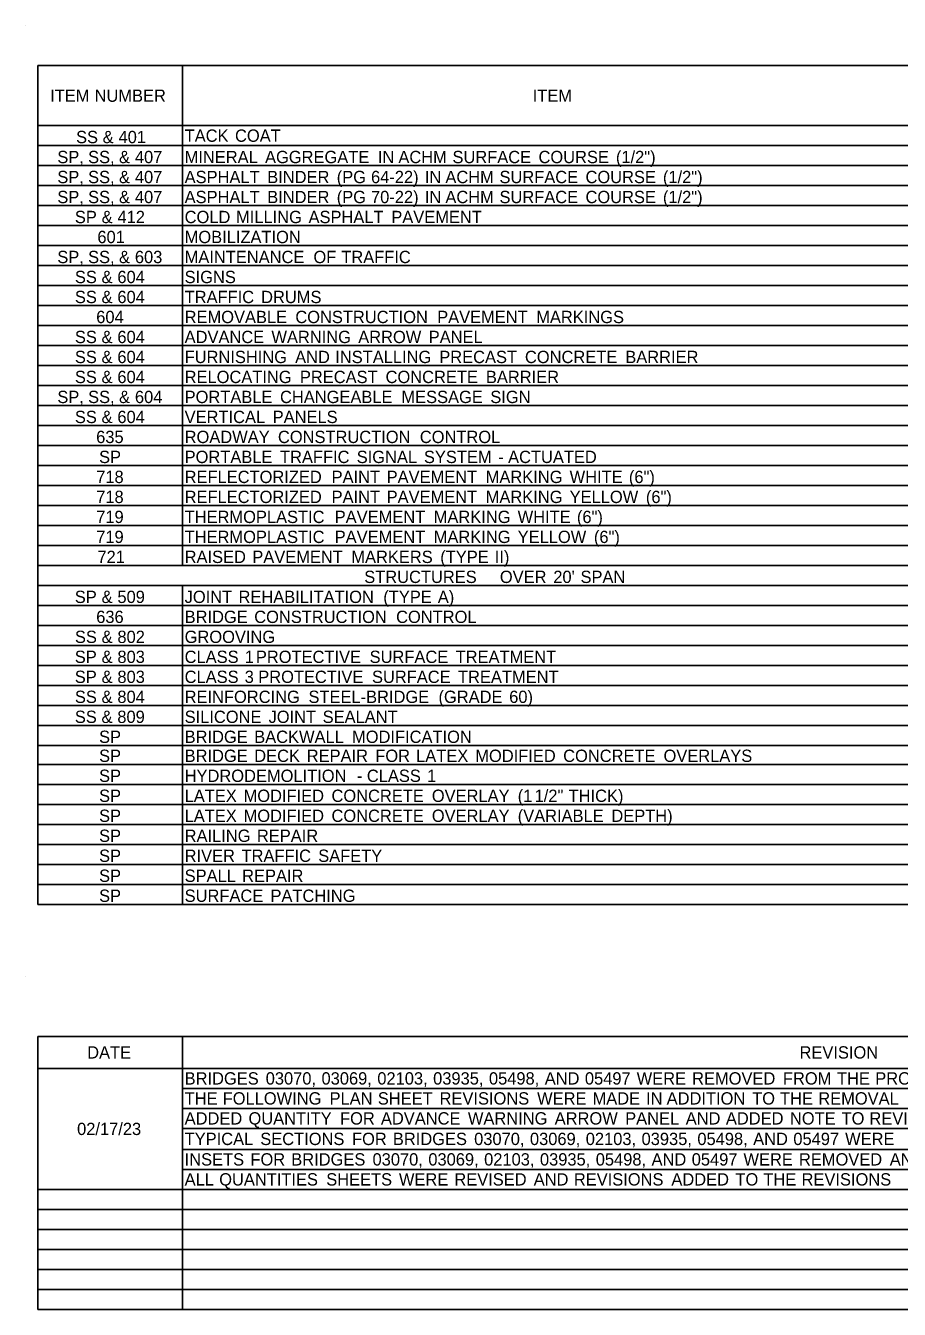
# Model space of a CAD drawing. Extents: x 544255 to 1930787, y -1947044 to 596640.
# Drawn here: x 555892 to 556318, y -1946820 to -1946194 of the extents above; entities that cross this region are included whole.
import ezdxf

# ---------------------------------------------------------------- set-up
doc = ezdxf.new("R2010")
doc.units = 0
doc.layers.add('Default', color=7, linetype='Continuous')

msp = doc.modelspace()

# ---------------------------------------------------------------- linework, layer by layer
at = {"layer": 'Default'}
for p, q in [((555892.13, -1946194.14), (555892.13, -1946194.14)), ((555897.98, -1946213.64), (556904.18, -1946213.64)), ((555897.98, -1946622.65), (555897.98, -1946213.64)), ((555897.98, -1946622.65), (555897.98, -1946213.64)), ((555968.66, -1946213.64), (556268.48, -1946213.64)), ((555968.66, -1946457.39), (555968.66, -1946213.64)), ((556268.48, -1946213.64), (556329.41, -1946213.64)), ((555897.98, -1946242.89), (556904.18, -1946242.89)), ((555897.98, -1946242.89), (556904.18, -1946242.89)), ((555968.66, -1946457.39), (555968.66, -1946242.89)), ((555897.98, -1946252.64), (556904.18, -1946252.64)), ((555897.98, -1946262.39), (556904.18, -1946262.39)), ((555897.98, -1946272.14), (556904.18, -1946272.14)), ((555897.98, -1946281.89), (556904.18, -1946281.89)), ((555897.98, -1946291.64), (556904.18, -1946291.64)), ((555897.98, -1946301.39), (556904.18, -1946301.39)), ((555897.98, -1946311.14), (556904.18, -1946311.14)), ((555897.98, -1946320.89), (556904.18, -1946320.89)), ((555897.98, -1946330.64), (556904.18, -1946330.64)), ((555897.98, -1946340.39), (556904.18, -1946340.39)), ((555897.98, -1946350.14), (556904.18, -1946350.14)), ((555897.98, -1946359.89), (556904.18, -1946359.89)), ((555897.98, -1946369.64), (556904.18, -1946369.64)), ((555897.98, -1946379.39), (556904.18, -1946379.39)), ((555897.98, -1946389.14), (556904.18, -1946389.14)), ((555897.98, -1946398.89), (556904.18, -1946398.89)), ((555897.98, -1946408.64), (556904.18, -1946408.64)), ((555897.98, -1946418.39), (556904.18, -1946418.39)), ((555897.98, -1946428.14), (556904.18, -1946428.14)), ((555897.98, -1946437.89), (556904.18, -1946437.89)), ((555897.98, -1946447.64), (556904.18, -1946447.64)), ((555897.98, -1946457.39), (556904.18, -1946457.39)), ((555897.98, -1946457.39), (556904.18, -1946457.39)), ((555897.98, -1946467.14), (556904.18, -1946467.14)), ((555897.98, -1946467.14), (556904.18, -1946467.14)), ((555968.66, -1946622.65), (555968.66, -1946467.14)), ((555897.98, -1946476.89), (556904.18, -1946476.89)), ((555897.98, -1946486.64), (556904.18, -1946486.64)), ((555897.98, -1946496.39), (556904.18, -1946496.39)), ((555897.98, -1946506.14), (556904.18, -1946506.14)), ((555897.98, -1946515.89), (556904.18, -1946515.89)), ((555897.98, -1946525.64), (556904.18, -1946525.64)), ((555897.98, -1946535.39), (556904.18, -1946535.39)), ((555897.98, -1946545.14), (556904.18, -1946545.14)), ((555897.98, -1946554.4), (556904.18, -1946554.4)), ((555897.98, -1946564.15), (556904.18, -1946564.15)), ((555897.98, -1946573.9), (556904.18, -1946573.9)), ((555897.98, -1946583.65), (556904.18, -1946583.65)), ((555897.98, -1946593.4), (556904.18, -1946593.4)), ((555897.98, -1946603.15), (556904.18, -1946603.15)), ((555897.98, -1946612.9), (556904.18, -1946612.9)), ((555897.98, -1946622.65), (556904.18, -1946622.65)), ((555892.13, -1946657.81), (555892.13, -1946657.81)), ((555897.98, -1946687.06), (556904.18, -1946687.06)), ((555897.98, -1946820.15), (555897.98, -1946687.06)), ((555897.98, -1946820.15), (555897.98, -1946687.06)), ((555968.66, -1946820.15), (555968.66, -1946687.06)), ((555897.98, -1946702.66), (556904.18, -1946702.66)), ((555968.66, -1946702.66), (556268.48, -1946702.66)), ((555968.66, -1946712.41), (556776.45, -1946712.41)), ((555968.66, -1946722.16), (556776.45, -1946722.16)), ((555968.66, -1946731.91), (556776.45, -1946731.91)), ((555968.66, -1946742.15), (556776.45, -1946742.15)), ((555968.66, -1946751.9), (556776.45, -1946751.9)), ((555897.98, -1946761.65), (556904.18, -1946761.65)), ((555897.98, -1946771.4), (556904.18, -1946771.4)), ((555897.98, -1946781.15), (556904.18, -1946781.15)), ((555897.98, -1946790.9), (556904.18, -1946790.9)), ((555897.98, -1946800.65), (556904.18, -1946800.65)), ((555897.98, -1946810.4), (556904.18, -1946810.4)), ((555897.98, -1946820.15), (556904.18, -1946820.15))]:
    msp.add_line(p, q, dxfattribs=at)

# ---------------------------------------------------------------- texts
for s, p in [('ITEM', (555904.07, -1946231.27)), (' NUMBER', (555923.49, -1946231.27)), ('ITEM', (556139.33, -1946231.27)), ('SS', (555916.7, -1946251.44)), (' &', (555927.45, -1946251.44)), (' 401', (555935.18, -1946251.44)), ('TACK', (555969.64, -1946250.77)), (' COAT', (555991.98, -1946250.77)), ('SP,', (555907.56, -1946261.19)), (' SS,', (555920.33, -1946261.19)), (' &', (555935.42, -1946261.19)), (' 407', (555943.15, -1946261.19)), ('MINERAL', (555969.64, -1946261.19)), (' AGGREGATE', (556006.61, -1946261.19)), (' IN', (556061.6, -1946261.19)), (' ACHM', (556071.63, -1946261.19)), (' SURFACE', (556098.01, -1946261.19)), (' COURSE', (556139.95, -1946261.19)), (' (1/2")', (556177.71, -1946261.19)), ('SP,', (555907.56, -1946270.94)), (' SS,', (555920.33, -1946270.94)), (' &', (555935.42, -1946270.94)), (' 407', (555943.15, -1946270.94)), ('ASPHALT', (555969.64, -1946270.94)), (' BINDER', (556007.68, -1946270.94)), (' (PG', (556041.57, -1946270.94)), (' 64-22)', (556058.28, -1946270.94)), (' IN', (556084.52, -1946270.94)), (' ACHM', (556094.55, -1946270.94)), (' SURFACE', (556120.93, -1946270.94)), (' COURSE', (556162.87, -1946270.94)), (' (1/2")', (556200.63, -1946270.94)), ('SP,', (555907.56, -1946280.69)), (' SS,', (555920.33, -1946280.69)), (' &', (555935.42, -1946280.69)), (' 407', (555943.15, -1946280.69)), ('ASPHALT', (555969.64, -1946280.69)), (' BINDER', (556007.68, -1946280.69)), (' (PG', (556041.57, -1946280.69)), (' 70-22)', (556058.28, -1946280.69)), (' IN', (556084.52, -1946280.69)), (' ACHM', (556094.55, -1946280.69)), (' SURFACE', (556120.93, -1946280.69)), (' COURSE', (556162.87, -1946280.69)), (' (1/2")', (556200.63, -1946280.69)), ('SP', (555916.11, -1946290.44)), (' &', (555926.93, -1946290.44)), (' 412', (555934.66, -1946290.44)), ('COLD', (555969.64, -1946290.44)), (' MILLING', (555992.48, -1946290.44)), (' ASPHALT', (556027.82, -1946290.44)), (' PAVEMENT', (556068.19, -1946290.44)), ('601', (555927.1, -1946300.19)), ('MOBILIZATION', (555969.64, -1946300.19)), ('SP,', (555907.56, -1946309.94)), (' SS,', (555920.33, -1946309.94)), (' &', (555935.42, -1946309.94)), (' 603', (555943.15, -1946309.94)), ('MAINTENANCE', (555969.64, -1946309.94)), (' OF', (556030.22, -1946309.94)), (' TRAFFIC', (556043.8, -1946309.94)), ('SS', (555916.13, -1946319.69)), (' &', (555926.88, -1946319.69)), (' 604', (555934.61, -1946319.69)), ('SIGNS', (555969.64, -1946319.69)), ('SS', (555916.13, -1946329.44)), (' &', (555926.88, -1946329.44)), (' 604', (555934.61, -1946329.44)), ('TRAFFIC', (555969.64, -1946329.44)), (' DRUMS', (556004.7, -1946329.44)), ('604', (555926.53, -1946339.19)), ('REMOVABLE', (555969.64, -1946339.19)), (' CONSTRUCTION', (556021.38, -1946339.19)), (' PAVEMENT', (556090.55, -1946339.19)), (' MARKINGS', (556138.84, -1946339.19)), ('SS', (555916.13, -1946348.94)), (' &', (555926.88, -1946348.94)), (' 604', (555934.61, -1946348.94)), ('ADVANCE', (555969.64, -1946348.94)), (' WARNING', (556009.73, -1946348.94)), (' ARROW', (556052.05, -1946348.94)), (' PANEL', (556086.42, -1946348.94)), ('SS', (555916.13, -1946358.69)), (' &', (555926.88, -1946358.69)), (' 604', (555934.61, -1946358.69)), ('FURNISHING', (555969.64, -1946358.69)), (' AND', (556021.28, -1946358.69)), (' INSTALLING', (556040.86, -1946358.69)), (' PRECAST', (556091.58, -1946358.69)), (' CONCRETE', (556133.34, -1946358.69)), (' BARRIER', (556182.27, -1946358.69)), ('SS', (555916.13, -1946368.44)), (' &', (555926.88, -1946368.44)), (' 604', (555934.61, -1946368.44)), ('RELOCATING', (555969.64, -1946368.44)), (' PRECAST', (556023.62, -1946368.44)), (' CONCRETE', (556065.38, -1946368.44)), (' BARRIER', (556114.31, -1946368.44)), ('SP,', (555907.57, -1946378.19)), (' SS,', (555920.34, -1946378.19)), (' &', (555935.44, -1946378.19)), (' 604', (555943.17, -1946378.19)), ('PORTABLE', (555969.64, -1946378.19)), (' CHANGEABLE', (556013.92, -1946378.19)), (' MESSAGE', (556073.11, -1946378.19)), (' SIGN', (556116.46, -1946378.19)), ('SS', (555916.13, -1946387.94)), (' &', (555926.88, -1946387.94)), (' 604', (555934.61, -1946387.94)), ('VERTICAL', (555969.64, -1946387.94)), (' PANELS', (556010.34, -1946387.94)), ('635', (555926.5, -1946397.69)), ('ROADWAY', (555969.64, -1946397.69)), (' CONSTRUCTION', (556012.9, -1946397.69)), (' CONTROL', (556082.08, -1946397.69)), ('SP', (555927.91, -1946407.44)), ('PORTABLE', (555969.64, -1946407.44)), (' TRAFFIC', (556013.92, -1946407.44)), (' SIGNAL', (556051.31, -1946407.44)), (' SYSTEM', (556084.09, -1946407.44)), (' ACTUATED', (556125.12, -1946407.44)), (' -', (556120.27, -1946407.44)), (' (6")', (556184.02, -1946417.19)), ('718', (555926.52, -1946417.19)), ('REFLECTORIZED', (555969.64, -1946417.19)), (' PAINT', (556039.07, -1946417.19)), (' PAVEMENT', (556065.91, -1946417.19)), (' MARKING', (556114.2, -1946417.19)), (' WHITE', (556155.13, -1946417.19)), ('718', (555926.52, -1946426.94)), ('REFLECTORIZED', (555969.64, -1946426.94)), (' PAINT', (556039.07, -1946426.94)), (' PAVEMENT', (556065.91, -1946426.94)), (' MARKING', (556114.2, -1946426.94)), (' YELLOW', (556155.13, -1946426.94)), (' (6")', (556192.3, -1946426.94)), ('719', (555926.52, -1946436.69)), ('THERMOPLASTIC', (555969.64, -1946436.69)), (' PAVEMENT', (556040.58, -1946436.69)), (' MARKING', (556088.86, -1946436.69)), (' WHITE', (556129.79, -1946436.69)), (' (6")', (556158.68, -1946436.69)), ('719', (555926.52, -1946446.44)), ('THERMOPLASTIC', (555969.64, -1946446.44)), (' PAVEMENT', (556040.58, -1946446.44)), (' MARKING', (556088.86, -1946446.44)), (' YELLOW', (556129.79, -1946446.44)), (' (6")', (556166.96, -1946446.44)), ('721', (555927.1, -1946456.19)), ('RAISED', (555969.64, -1946456.19)), (' PAVEMENT', (556000.41, -1946456.19)), (' MARKERS', (556048.69, -1946456.19)), (' (TYPE', (556092.05, -1946456.19)), (' II)', (556118.62, -1946456.19)), ('                                                                       STRUCTURES', (555898.95, -1946465.94)), (' OVER', (556121.11, -1946465.94)), (" 20'", (556147.16, -1946465.94)), (' SPAN', (556160.43, -1946465.94)), ('SP', (555916.08, -1946475.69)), (' &', (555926.9, -1946475.69)), (' 509', (555934.63, -1946475.69)), ('JOINT', (555969.64, -1946475.69)), (' REHABILITATION', (555993.69, -1946475.69)), (' (TYPE', (556064.28, -1946475.69)), (' A)', (556090.85, -1946475.69)), ('636', (555926.52, -1946485.44)), ('BRIDGE', (555969.64, -1946485.44)), (' CONSTRUCTION', (556001.34, -1946485.44)), (' CONTROL', (556070.51, -1946485.44)), ('SS', (555916.15, -1946495.19)), (' &', (555926.9, -1946495.19)), (' 802', (555934.63, -1946495.19)), ('GROOVING', (555969.64, -1946495.19)), ('SP', (555916.08, -1946504.94)), (' &', (555926.9, -1946504.94)), (' 803', (555934.63, -1946504.94)), ('CLASS', (555969.64, -1946504.94)), (' 1', (555996.69, -1946504.94)), (' PROTECTIVE', (556002.14, -1946504.94)), (' SURFACE', (556057.6, -1946504.94)), (' TREATMENT', (556099.54, -1946504.94)), ('SP', (555916.08, -1946514.69)), (' &', (555926.9, -1946514.69)), (' 803', (555934.63, -1946514.69)), ('CLASS', (555969.64, -1946514.69)), (' 3', (555996.69, -1946514.69)), (' PROTECTIVE', (556003.3, -1946514.69)), (' SURFACE', (556058.76, -1946514.69)), (' TREATMENT', (556100.7, -1946514.69)), ('SS', (555916.13, -1946524.44)), (' &', (555926.88, -1946524.44)), (' 804', (555934.61, -1946524.44)), ('REINFORCING', (555969.64, -1946524.44)), (' STEEL-BRIDGE', (556027.8, -1946524.44)), (' (GRADE', (556091.18, -1946524.44)), (' 60)', (556125.66, -1946524.44)), ('SS', (555916.11, -1946534.19)), (' &', (555926.86, -1946534.19)), (' 809', (555934.59, -1946534.19)), ('SILICONE', (555969.64, -1946534.19)), (' JOINT', (556008.32, -1946534.19)), (' SEALANT', (556034.7, -1946534.19)), ('SP', (555927.91, -1946543.94)), ('BRIDGE', (555969.64, -1946543.94)), (' BACKWALL', (556001.34, -1946543.94)), (' MODIFICATION', (556049.03, -1946543.94)), ('SP', (555927.91, -1946553.2)), ('BRIDGE', (555969.64, -1946553.2)), (' DECK', (556001.34, -1946553.2)), (' REPAIR', (556026.94, -1946553.2)), (' FOR', (556060.37, -1946553.2)), (' LATEX', (556080.28, -1946553.2)), (' MODIFIED', (556109.12, -1946553.2)), (' CONCRETE', (556151.98, -1946553.2)), (' OVERLAYS', (556200.91, -1946553.2)), ('SP', (555927.91, -1946562.95)), ('HYDRODEMOLITION', (555969.64, -1946562.95)), (' -', (556051.4, -1946562.95)), (' CLASS', (556056.26, -1946562.95)), (' 1', (556085.64, -1946562.95)), ('SP', (555927.91, -1946572.7)), ('LATEX', (555969.64, -1946572.7)), (' MODIFIED', (555996.15, -1946572.7)), (' CONCRETE', (556039.01, -1946572.7)), (' OVERLAY', (556087.94, -1946572.7)), (' (1', (556129.81, -1946572.7)), (' 1/2"', (556138.05, -1946572.7)), (' THICK)', (556154.61, -1946572.7)), ('SP', (555927.91, -1946582.45)), ('LATEX', (555969.64, -1946582.45)), (' MODIFIED', (555996.15, -1946582.45)), (' CONCRETE', (556039.01, -1946582.45)), (' OVERLAY', (556087.94, -1946582.45)), (' (VARIABLE', (556129.81, -1946582.45)), (' DEPTH)', (556175.49, -1946582.45)), ('SP', (555927.91, -1946592.2)), ('RAILING', (555969.64, -1946592.2)), (' REPAIR', (556002.65, -1946592.2)), ('SP', (555927.91, -1946601.95)), ('RIVER', (555969.64, -1946601.95)), (' TRAFFIC', (555995.15, -1946601.95)), (' SAFETY', (556032.54, -1946601.95)), ('SP', (555927.91, -1946611.7)), ('SPALL', (555969.64, -1946611.7)), (' REPAIR', (555995.44, -1946611.7)), ('SP', (555927.91, -1946621.45)), ('SURFACE', (555969.64, -1946621.45)), (' PATCHING', (556009.26, -1946621.45)), ('DATE', (555922.12, -1946697.86)), ('REVISION', (556269.45, -1946697.86)), ('BRIDGES', (555969.64, -1946710.53)), (' 03070,', (556006.94, -1946710.53)), (' 03069,', (556034.15, -1946710.53)), (' 02103,', (556061.36, -1946710.53)), (' 03935,', (556088.57, -1946710.53)), (' 05498,', (556115.78, -1946710.53)), (' AND', (556142.99, -1946710.53)), (' 05497', (556162.57, -1946710.53)), (' WERE', (556187.82, -1946710.53)), (' REMOVED', (556214.85, -1946710.53)), (' FROM', (556259.13, -1946710.53)), (' THE', (556285.5, -1946710.53)), (' PROJECT', (556304.15, -1946710.53)), ('THE', (555969.64, -1946720.28)), (' FOLLOWING', (555985.96, -1946720.28)), (' PLAN', (556038.06, -1946720.28)), (' SHEET', (556061.61, -1946720.28)), (' REVISIONS', (556091.72, -1946720.28)), (' WERE', (556139.27, -1946720.28)), (' MADE', (556166.3, -1946720.28)), (' IN', (556192.4, -1946720.28)), (' ADDITION', (556202.43, -1946720.28)), (' TO', (556244.13, -1946720.28)), (' THE', (556257.72, -1946720.28)), (' REMOVAL', (556276.37, -1946720.28)), ('02/17/23', (555917.2, -1946735.15)), ('ADDED', (555969.64, -1946730.03)), (' QUANTITY', (555998.54, -1946730.03)), (' FOR', (556043.19, -1946730.03)), (' ADVANCE', (556063.11, -1946730.03)), (' WARNING', (556105.52, -1946730.03)), (' ARROW', (556147.84, -1946730.03)), (' PANEL', (556182.21, -1946730.03)), (' AND', (556211.73, -1946730.03)), (' ADDED', (556231.32, -1946730.03)), (' NOTE', (556262.55, -1946730.03)), (' TO', (556287.72, -1946730.03)), (' REVISONS', (556301.31, -1946730.03)), ('TYPICAL', (555969.64, -1946740.03)), (' SECTIONS', (556004.29, -1946740.03)), (' FOR', (556049.03, -1946740.03)), (' BRIDGES', (556068.95, -1946740.03)), (' 03070,', (556108.57, -1946740.03)), (' 03069,', (556135.78, -1946740.03)), (' 02103,', (556162.99, -1946740.03)), (' 03935,', (556190.2, -1946740.03)), (' 05498,', (556217.41, -1946740.03)), (' AND', (556244.62, -1946740.03)), (' 05497', (556264.21, -1946740.03)), (' WERE', (556289.46, -1946740.03)), ('INSETS', (555969.64, -1946750.02)), (' FOR', (555999.48, -1946750.02)), (' BRIDGES', (556019.4, -1946750.02)), (' 03070,', (556059.02, -1946750.02)), (' 03069,', (556086.23, -1946750.02)), (' 02103,', (556113.44, -1946750.02)), (' 03935,', (556140.65, -1946750.02)), (' 05498,', (556167.86, -1946750.02)), (' AND', (556195.07, -1946750.02)), (' 05497', (556214.66, -1946750.02)), (' WERE', (556239.9, -1946750.02)), (' REMOVED', (556266.94, -1946750.02)), (' AND', (556311.21, -1946750.02)), ('ALL', (555969.64, -1946759.77)), (' QUANTITIES', (555984.26, -1946759.77)), (' SHEETS', (556036.45, -1946759.77)), (' WERE', (556071.89, -1946759.77)), (' REVISED', (556098.92, -1946759.77)), (' AND', (556137.61, -1946759.77)), (' REVISIONS', (556157.19, -1946759.77)), (' ADDED', (556204.74, -1946759.77)), (' TO', (556235.97, -1946759.77)), (' THE', (556249.57, -1946759.77)), (' REVISIONS', (556268.22, -1946759.77))]:
    msp.add_text(s, height=6, dxfattribs=at).set_placement(p)

doc.saveas('drawing.dxf')
